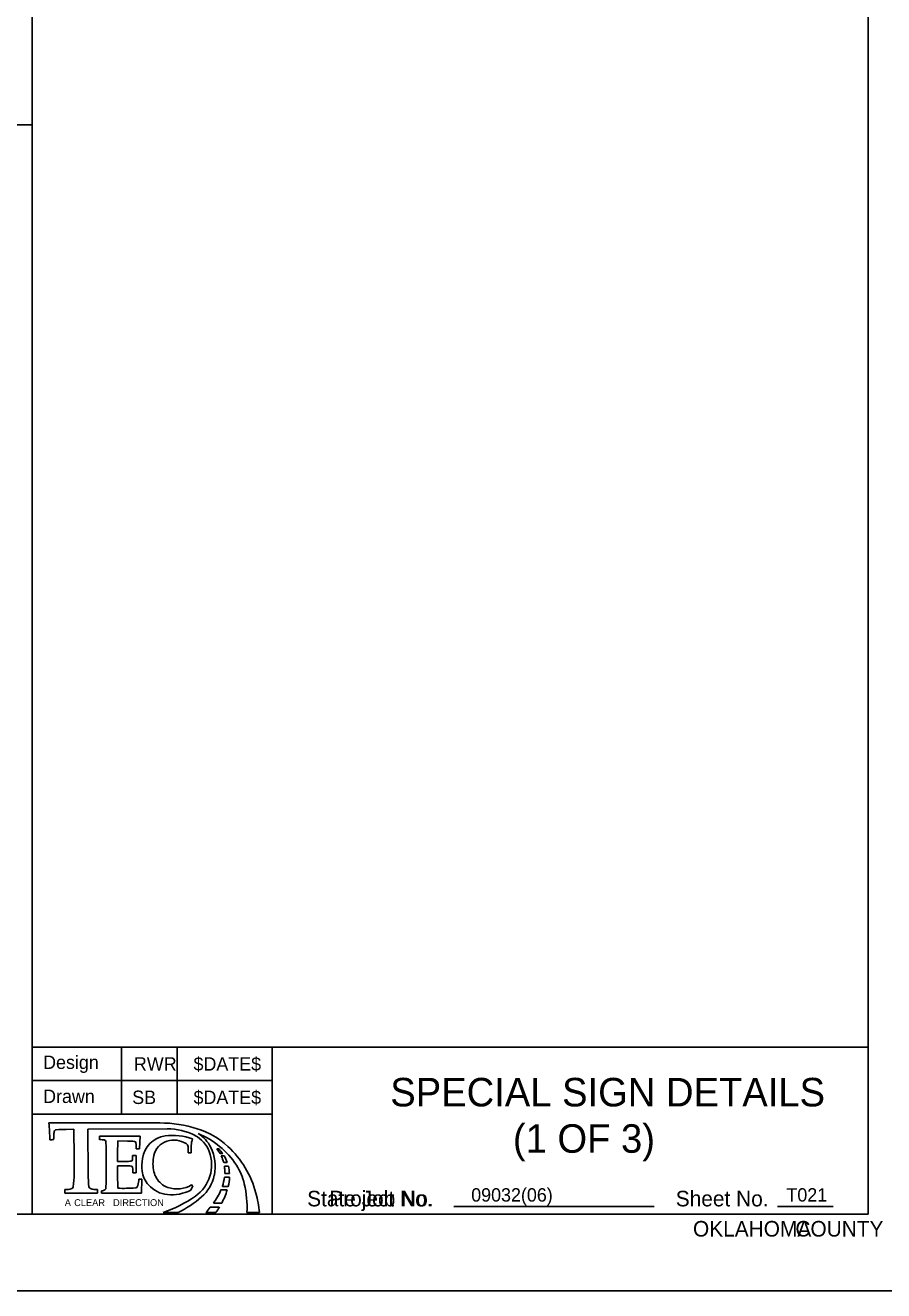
# Model space of a CAD drawing. Extents: x 2149961 to 2150220, y 145114 to 145240.
# Drawn here: x 2150135.1 to 2150172.2, y 145114.1 to 145168.7 of the extents above; entities that cross this region are included whole.
import ezdxf

# ---------------------------------------------------------------- set-up
doc = ezdxf.new("R2010")
doc.units = 0
for name, color, linetype in [('BORDER', 7, 'Continuous'), ('DATE', 7, 'Continuous'), ('Level 1', 7, 'Continuous'), ('PDF', 7, 'Continuous'), ('project no', 7, 'Continuous'), ('state job no', 7, 'Continuous'), ('TEC LOGO', 7, 'Continuous'), ('TEXT', 7, 'Continuous')]:
    doc.layers.add(name, color=color, linetype=linetype)

msp = doc.modelspace()

# ---------------------------------------------------------------- linework, layer by layer
at = {"layer": 'BORDER'}
for p, q in [((2150171.536, 145117.388), (2150171.536, 145216.512)), ((2150171.536, 145124.606), (2150135.447, 145124.606)), ((2150135.447, 145124.606), (2150135.447, 145117.388)), ((2150139.297, 145124.606), (2150139.297, 145121.719)), ((2150141.703, 145121.719), (2150141.703, 145124.606)), ((2150145.8, 145117.359), (2150145.8, 145124.577)), ((2150135.447, 145123.162), (2150145.8, 145123.162)), ((2150135.447, 145121.719), (2150145.8, 145121.719)), ((2150153.637, 145117.729), (2150162.298, 145117.729)), ((2150167.618, 145117.729), (2150170.024, 145117.729)), ((2150017.557, 145117.388), (2150171.536, 145117.388)), ((2150171.536, 145117.388), (2150171.536, 145117.388)), ((2150010.458, 145114.088), (2150174.061, 145114.088))]:
    msp.add_line(p, q, dxfattribs=at)
at = {"layer": 'Level 1'}
for p, q in [((2150135.447, 145216.512), (2150135.447, 145124.606)), ((2150120.969, 145164.445), (2150135.447, 145164.445))]:
    msp.add_line(p, q, dxfattribs=at)
at = {"layer": 'PDF'}
msp.add_lwpolyline([(2150010.458, 145114.088), (2150174.061, 145114.088), (2150174.061, 145219.948), (2150010.458, 145219.948)], close=True, dxfattribs=at)
at = {"layer": 'TEC LOGO'}
for p, q in [((2150136.163, 145121.335), (2150140.955, 145121.335)), ((2150137.238, 145121.058), (2150136.905, 145121.056)), ((2150141.264, 145121.082), (2150137.847, 145121.062)), ((2150137.847, 145121.062), (2150137.86, 145119.111)), ((2150138.352, 145120.759), (2150138.349, 145120.611)), ((2150140.106, 145120.759), (2150138.352, 145120.759)), ((2150139.134, 145120.555), (2150139.56, 145120.552)), ((2150140.07, 145120.219), (2150140.106, 145120.759)), ((2150142.307, 145120.354), (2150142.3, 145120.043)), ((2150139.925, 145119.934), (2150139.778, 145119.934)), ((2150139.925, 145120.219), (2150140.07, 145120.219)), ((2150139.925, 145119.172), (2150139.925, 145119.934)), ((2150142.3, 145120.043), (2150142.168, 145120.048)), ((2150143.414, 145120.213), (2150143.504, 145120.213)), ((2150143.669, 145120.008), (2150143.554, 145120.008)), ((2150143.731, 145119.909), (2150143.606, 145119.909)), ((2150143.709, 145119.627), (2150143.862, 145119.627)), ((2150143.74, 145119.471), (2150143.909, 145119.471)), ((2150139.785, 145119.172), (2150139.925, 145119.172)), ((2150140.175, 145118.91), (2150140.043, 145118.91)), ((2150140.159, 145118.3), (2150140.175, 145118.91)), ((2150143.743, 145118.997), (2150143.958, 145118.997)), ((2150143.957, 145119.151), (2150143.755, 145119.151)), ((2150136.856, 145118.3), (2150136.856, 145118.452)), ((2150138.255, 145118.3), (2150136.856, 145118.3)), ((2150138.255, 145118.452), (2150138.255, 145118.3)), ((2150138.439, 145118.399), (2150138.43, 145118.3)), ((2150138.43, 145118.3), (2150140.159, 145118.3)), ((2150142.374, 145118.62), (2150142.288, 145118.435)), ((2150142.324, 145118.657), (2150142.374, 145118.62)), ((2150143.86, 145118.438), (2150143.591, 145118.438)), ((2150143.903, 145118.595), (2150143.65, 145118.595)), ((2150143.52, 145117.689), (2150143.126, 145117.689)), ((2150143.264, 145117.867), (2150143.623, 145117.867)), ((2150141.747, 145117.467), (2150141.099, 145117.467)), ((2150142.942, 145117.467), (2150143.375, 145117.467)), ((2150145.252, 145117.467), (2150144.714, 145117.467))]:
    msp.add_line(p, q, dxfattribs=at)
for centre, radius, start, end in [((2150129.713, 145120.639), 6.487, 359.663, 6.1563), ((2150137.218, 145120.781), 0.843, 167.5337, 178.5623), ((2150136.49, 145120.942), 0.0962, 94.698, 167.5337), ((2150136.937, 145115.493), 5.563, 90.3367, 94.698), ((2150046.46, 145119.478), 90.791, 359.77628, 0.99712), ((2150140.955, 145116.038), 5.297, 72.2522, 90), ((2150141.28, 145118.51), 2.573, 62.4303, 90.3367), ((2150141.492, 145117.716), 3.535, 47.2839, 72.2522), ((2150141.269, 145117.57), 3.562, 32.9982, 68.0651), ((2150141.873, 145119.647), 1.426, 26.3065, 59.3722), ((2150136.235, 145120.976), 0.377, 264.6321, 291.5899), ((2150142.861, 145120.639), 6.487, 178.5623, 180.1181), ((2150138.383, 145119.475), 1.137, 80.6874, 91.7186), ((2150138.555, 145120.525), 0.0722, 1.4011, 80.6874), ((2150097.794, 145119.528), 40.845, 358.5952, 1.4011), ((2150222.857, 145119.533), 83.729, 179.30064, 179.90313), ((2150139.538, 145117.558), 2.995, 83.8831, 89.5816), ((2150139.849, 145120.463), 0.0722, 5.4112, 83.8831), ((2150138.327, 145120.319), 1.601, 356.4205, 5.4112), ((2150141.338, 145119.635), 1.149, 97.9231, 172.0344), ((2150141.512, 145119.746), 0.839, 107.7088, 167.9528), ((2150141.514, 145118.371), 2.426, 69.3982, 97.9231), ((2150141.562, 145119.589), 1.004, 58.2676, 107.7088), ((2150141.997, 145120.293), 0.176, 2.4202, 58.2676), ((2150143.117, 145120.335), 0.81, 157.7575, 178.6366), ((2150141.873, 145119.647), 1.289, 20.6867, 62.4303), ((2150141.052, 145117.24), 4.183, 14.7043, 47.2839), ((2150138.932, 145119.89), 0.847, 349.9583, 3.0005), ((2150142.345, 145119.494), 2.166, 172.0344, 186.3105), ((2150142.25, 145119.588), 1.594, 167.9528, 193.0838), ((2150140.098, 145120.213), 2.077, 355.4457, 2.4202), ((2150141.537, 145119.52), 1.649, 305.1645, 20.6867), ((2150141.484, 145119.455), 1.86, 348.2376, 26.3065), ((2150142.22, 145119.245), 1.536, 29.7365, 39.0219), ((2150142.29, 145119.068), 1.669, 34.2695, 43.3207), ((2150142.22, 145119.245), 1.536, 14.3628, 25.5725), ((2150142.29, 145119.068), 1.669, 19.5618, 30.2542), ((2150139.363, 145128.515), 8.844, 268.4788, 271.5206), ((2150139.362, 145110.642), 8.844, 88.4794, 91.5212), ((2150222.857, 145119.533), 83.729, 180.03409, 180.69936), ((2150139.572, 145120.641), 0.967, 271.5206, 277.9096), ((2150139.571, 145118.517), 0.967, 81.2846, 88.4794), ((2150139.695, 145119.755), 0.0722, 277.9096, 349.9583), ((2150139.707, 145119.401), 0.0722, 5.6885, 81.2846), ((2150138.141, 145119.245), 1.646, 357.4607, 5.6885), ((2150141.269, 145119.375), 1.083, 186.3105, 221.5776), ((2150141.645, 145119.448), 0.973, 193.0838, 228.7889), ((2150142.22, 145119.245), 1.536, 2.0409, 8.4283), ((2150141.804, 145119.231), 1.952, 357.6694, 2.0409), ((2150142.29, 145119.068), 1.669, 2.8667, 13.9687), ((2150142.146, 145118.139), 2.517, 12.951, 32.9982), ((2150132.45, 145119.143), 4.801, 353.2347, 359.7763), ((2150142.661, 145119.143), 4.801, 180.3775, 186.7653), ((2150139.168, 145118.894), 0.876, 342.6077, 1.0782), ((2150141.577, 145119.37), 0.87, 228.7889, 251.3711), ((2150141.651, 145119.42), 1.689, 310.5997, 348.2376), ((2150141.804, 145119.231), 1.952, 341.0487, 353.1199), ((2150142.049, 145119.055), 1.911, 346.0491, 358.2376), ((2150142.049, 145119.055), 1.911, 2.8951, 2.9107), ((2150140.037, 145117.654), 4.681, 357.7052, 12.951), ((2150136.867, 145119.381), 0.929, 269.3409, 287.8364), ((2150137.122, 145118.588), 0.0962, 287.8364, 353.2347), ((2150137.989, 145118.588), 0.0962, 186.7653, 252.1636), ((2150138.244, 145119.381), 0.929, 252.1636, 270.6591), ((2150138.412, 145118.712), 0.314, 274.8598, 303.0633), ((2150138.531, 145118.529), 0.0962, 303.0633, 358.5952), ((2150139.369, 145127.352), 8.844, 268.4788, 273.4332), ((2150139.893, 145118.62), 0.0962, 273.4332, 326.9687), ((2150139.753, 145118.711), 0.263, 326.9687, 342.6077), ((2150141.404, 145119.495), 1.263, 221.5776, 264.5103), ((2150139.346, 145122.63), 5.453, 288.7522, 305.1645), ((2150141.454, 145120.022), 1.792, 264.5103, 297.7193), ((2150141.691, 145119.707), 1.226, 251.3711, 301.0817), ((2150139.464, 145121.971), 5.05, 296.8707, 310.5997), ((2150141.152, 145119.455), 2.643, 323.1081, 337.382), ((2150140.843, 145119.355), 3.152, 331.8459, 343.1036), ((2150141.152, 145119.455), 2.643, 341.0109, 341.0487), ((2150140.843, 145119.355), 3.152, 346.0548, 346.0603), ((2150139.621, 145116.864), 5.663, 6.1104, 14.7043), ((2150137.249, 145122.384), 7.522, 319.179, 321.3834), ((2150137.249, 145122.384), 7.522, 323.0973, 323.1081), ((2150137.725, 145121.305), 6.831, 325.8118, 328.04), ((2150140.843, 145119.355), 3.152, 327.9791, 328.0787)]:
    msp.add_arc(centre, radius, start, end, dxfattribs=at)

# ---------------------------------------------------------------- texts
at = {"layer": 'BORDER'}
for s, height, p in [('Design', 0.5774, (2150135.913, 145123.665)), ('RWR', 0.5774, (2150139.833, 145123.596)), ('Drawn', 0.5774, (2150135.913, 145122.195)), ('SB ', 0.5774, (2150139.76, 145122.152)), ('09032(06)      ', 0.57742, (2150154.394, 145117.937)), ('Sheet No.', 0.6737, (2150163.225, 145117.729)), (' T021', 0.5774, (2150167.786, 145117.937)), ('       OKLAHOMA', 0.67366, (2150162.216, 145116.426)), (' COUNTY', 0.6737, (2150168.138, 145116.426))]:
    msp.add_text(s, height=height, dxfattribs=at).set_placement(p)
at = {"layer": 'DATE'}
for p in [(2150142.406, 145123.595), (2150142.406, 145122.152)]:
    msp.add_text('$DATE$', height=0.5774, dxfattribs=at).set_placement(p)
at = {"layer": 'project no'}
msp.add_text('Project No.', height=0.67366, dxfattribs=at).set_placement((2150148.267, 145117.729))
at = {"layer": 'state job no'}
msp.add_text('State Job No.', height=0.67366, dxfattribs=at).set_placement((2150147.312, 145117.729))
at = {"layer": 'TEC LOGO'}
for s, height, p in [('A', 0.298, (2150136.847, 145117.742)), ('CLEAR', 0.2983, (2150137.254, 145117.742)), ('DIRECTION', 0.2983, (2150138.933, 145117.742))]:
    msp.add_text(s, height=height, dxfattribs=at).set_placement(p)
at = {"layer": 'TEXT'}
for s, p in [('SPECIAL SIGN DETAILS', (2150150.9, 145122.047)), ('(1 OF 3)', (2150156.194, 145120.045))]:
    msp.add_text(s, height=1.232, dxfattribs=at).set_placement(p)

doc.saveas('drawing.dxf')
